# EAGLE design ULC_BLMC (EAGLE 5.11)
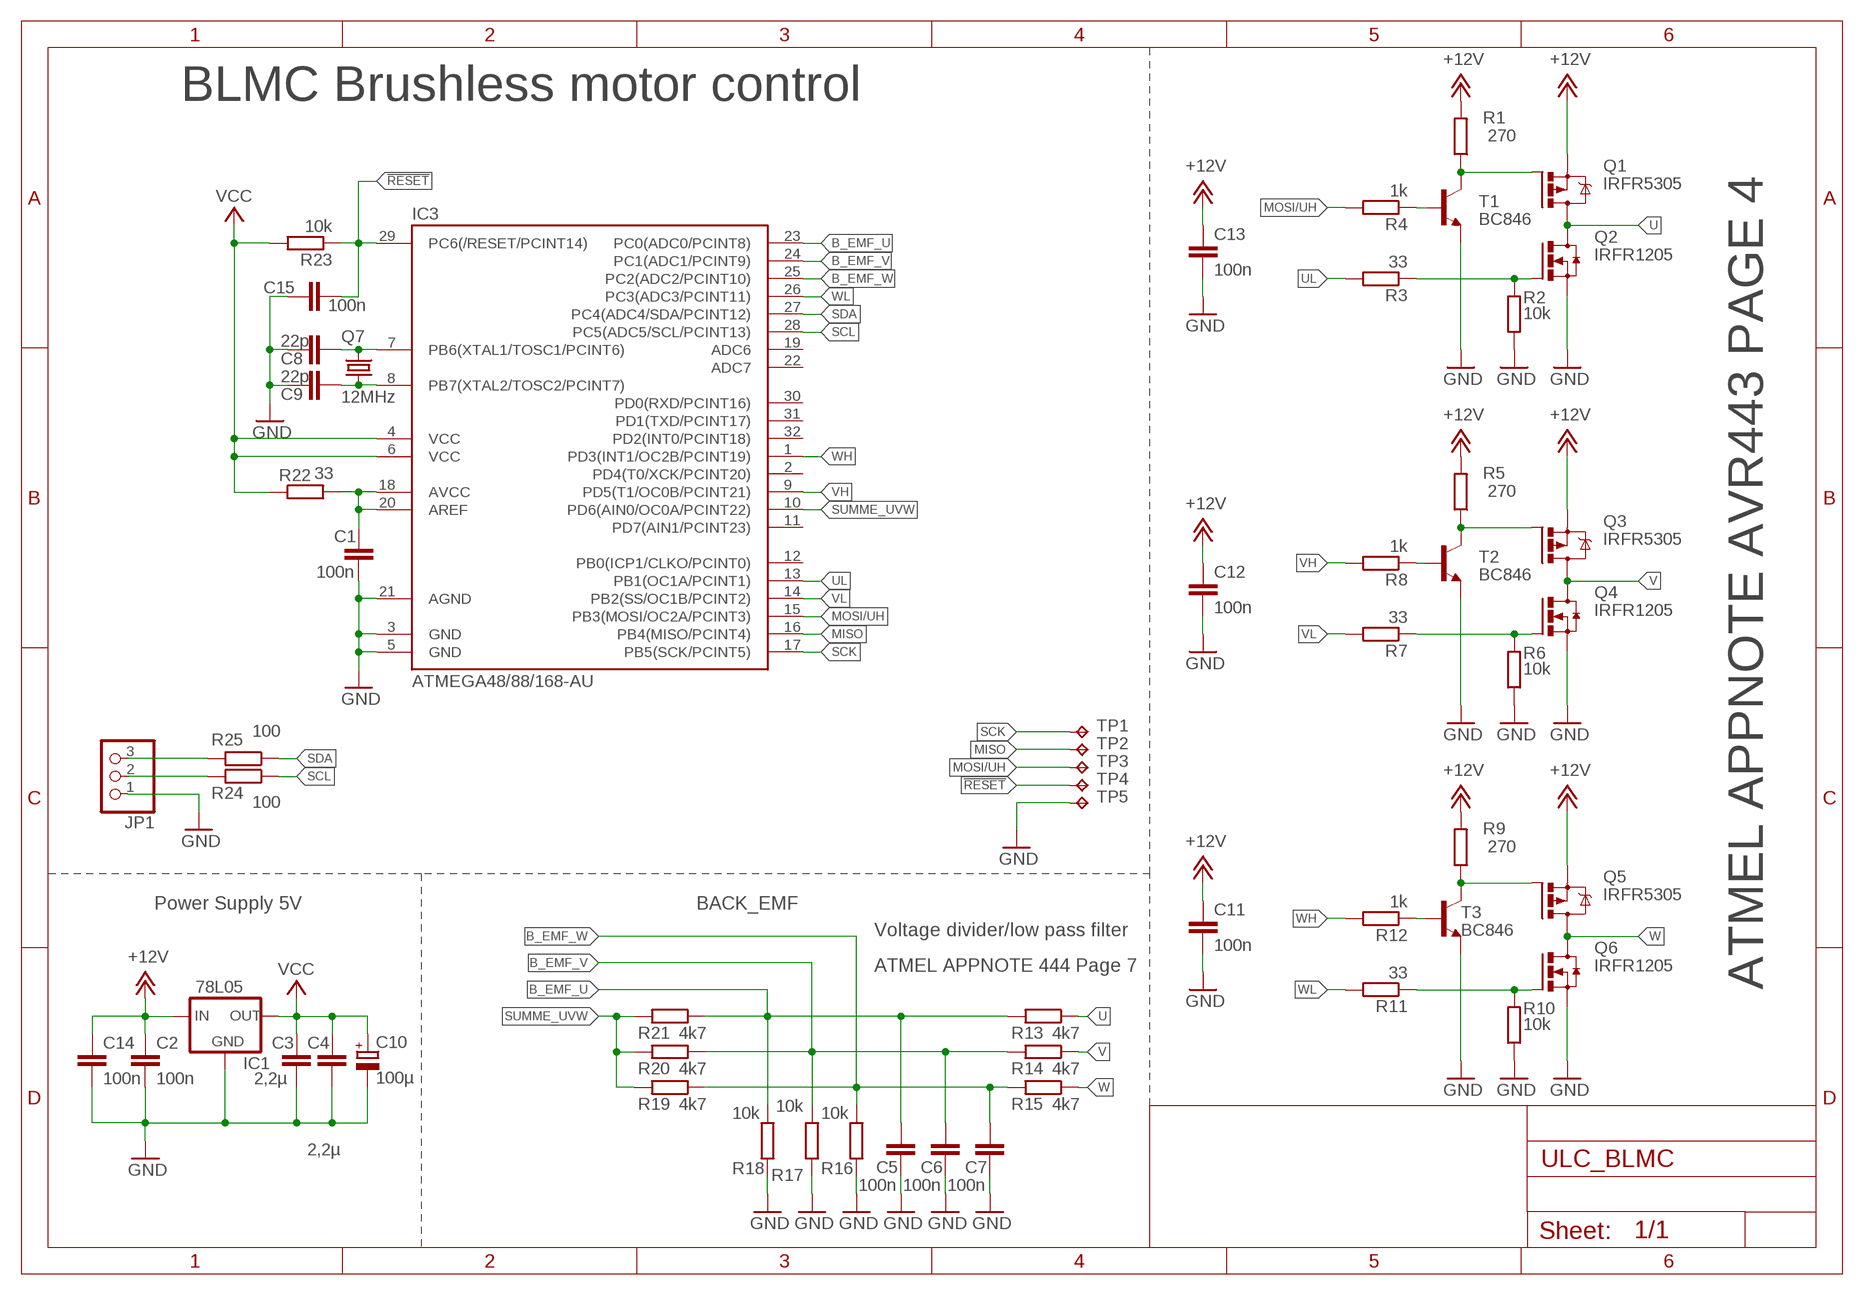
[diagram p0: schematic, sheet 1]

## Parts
C1  100n  C-EUC0805  [C0805]
C2  100n  C-EUC0805  [C0805]
C3  2,2µ  C-EUC0805  [C0805]
C4  2,2µ  C-EUC0805  [C0805]
C5  100n  C-EUC0805  [C0805]
C6  100n  C-EUC0805  [C0805]
C7  100n  C-EUC0805  [C0805]
C8  22p  C-EUC0805  [C0805]
C9  22p  C-EUC0805  [C0805]
C10  100µ  CPOL-EUSMCE  [SMC_E]
C11  100n  C-EUC0805  [C0805]
C12  100n  C-EUC0805  [C0805]
C13  100n  C-EUC0805  [C0805]
C14  100n  C-EUC0805  [C0805]
C15  100n  C-EUC0805  [C0805]
IC1  78L05  78LXX  [78LXX]
IC3  ATMEGA48/88/168-AU  [TQFP32-08]
JP1  PINHD-1X3  [1X03]
Q1  IRFR5305  [D-PAK_TO252AA]
Q2  IRFR1205  [D-PAK_TO252AA]
Q3  IRFR5305  [D-PAK_TO252AA]
Q4  IRFR1205  [D-PAK_TO252AA]
Q5  IRFR5305  [D-PAK_TO252AA]
Q6  IRFR1205  [D-PAK_TO252AA]
Q7  12MHz  CRYSTALCTS406  [CTS406]
R1  270  R-EU_M0805  [M0805]
R2  10k  R-EU_M0805  [M0805]
R3  33  R-EU_M0805  [M0805]
R4  1k  R-EU_M0805  [M0805]
R5  270  R-EU_M0805  [M0805]
R6  10k  R-EU_M0805  [M0805]
R7  33  R-EU_M0805  [M0805]
R8  1k  R-EU_M0805  [M0805]
R9  270  R-EU_M0805  [M0805]
R10  10k  R-EU_M0805  [M0805]
R11  33  R-EU_M0805  [M0805]
R12  1k  R-EU_M0805  [M0805]
R13  4k7  R-EU_M0805  [M0805]
R14  4k7  R-EU_M0805  [M0805]
R15  4k7  R-EU_M0805  [M0805]
R16  10k  R-EU_M0805  [M0805]
R17  10k  R-EU_M0805  [M0805]
R18  10k  R-EU_M0805  [M0805]
R19  4k7  R-EU_M0805  [M0805]
R20  4k7  R-EU_M0805  [M0805]
R21  4k7  R-EU_M0805  [M0805]
R22  33  R-EU_M0805  [M0805]
R23  10k  R-EU_M0805  [M0805]
R24  100  R-EU_M0805  [M0805]
R25  100  R-EU_M0805  [M0805]
T1  BC846  [SOT23]
T2  BC846  [SOT23]
T3  BC846  [SOT23]
TP1  TPB1,27  [B1,27]
TP2  TPB1,27  [B1,27]
TP3  TPB1,27  [B1,27]
TP4  TPB1,27  [B1,27]
TP5  TPB1,27  [B1,27]

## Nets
!RESET: C15.2 IC3.29(PC6(/RESET/PCINT14)) R23.1 TP4.TP
+12V: C2.1 C11.1 C12.1 C13.1 C14.1 IC1.IN Q1.3(S) Q3.3(S) Q5.3(S) R1.2 R5.2 R9.2
B_EMF_U: C5.1 IC3.23(PC0(ADC0/PCINT8)) R13.2 R18.1 R21.1
B_EMF_V: C6.1 IC3.24(PC1(ADC1/PCINT9)) R14.2 R17.1 R20.1
B_EMF_W: C7.1 IC3.25(PC2(ADC2/PCINT10)) R15.2 R16.1 R19.1
GND: C1.2 C2.2 C3.2 C4.2 C5.2 C6.2 C7.2 C8.1 C9.1 C10.- C11.2 C12.2 C13.2 C14.2 C15.1 IC1.GND IC3.3(GND) IC3.5(GND) IC3.21(AGND) JP1.1 Q2.3(S) Q4.3(S) Q6.3(S) R2.1 R6.1 R10.1 R16.2 R17.2 R18.2 T1.2(E) T2.2(E) T3.2(E) TP5.TP
MISO: IC3.16(PB4(MISO/PCINT4)) TP2.TP
MOSI/UH: IC3.15(PB3(MOSI/OC2A/PCINT3)) R4.2 TP3.TP
N$1: Q6.1(G) R10.2 R11.1
N$2: R4.1 T1.1(B)
N$3: C1.1 IC3.18(AVCC) IC3.20(AREF) R22.2
N$4: Q1.1(G) R1.1 T1.3(C)
N$5: Q3.1(G) R5.1 T2.3(C)
N$6: Q4.1(G) R6.2 R7.1
N$7: R8.1 T2.1(B)
N$8: Q5.1(G) R9.1 T3.3(C)
N$9: Q2.1(G) R2.2 R3.1
N$10: R12.1 T3.1(B)
N$11: C8.2 IC3.7(PB6(XTAL1/TOSC1/PCINT6)) Q7.3
N$12: C9.2 IC3.8(PB7(XTAL2/TOSC2/PCINT7)) Q7.1
N$13: JP1.3 R25.2
N$14: JP1.2 R24.2
SCK: IC3.17(PB5(SCK/PCINT5)) TP1.TP
SCL: IC3.28(PC5(ADC5/SCL/PCINT13)) R24.1
SDA: IC3.27(PC4(ADC4/SDA/PCINT12)) R25.1
SUMME_UVW: IC3.10(PD6(AIN0/OC0A/PCINT22)) R19.2 R20.2 R21.2
U: Q1.4(D) Q2.4(D) R13.1
UL: IC3.13(PB1(OC1A/PCINT1)) R3.2
V: Q3.4(D) Q4.4(D) R14.1
VCC: C3.1 C4.1 C10.+ IC1.OUT IC3.4(VCC) IC3.6(VCC) R22.1 R23.2
VH: IC3.9(PD5(T1/OC0B/PCINT21)) R8.2
VL: IC3.14(PB2(SS/OC1B/PCINT2)) R7.2
W: Q5.4(D) Q6.4(D) R15.1
WH: IC3.1(PD3(INT1/OC2B/PCINT19)) R12.2
WL: IC3.26(PC3(ADC3/PCINT11)) R11.2
Unconnected: IC3.2(PD4(T0/XCK/PCINT20)) IC3.11(PD7(AIN1/PCINT23)) IC3.12(PB0(ICP1/CLKO/PCINT0)) IC3.19(ADC6) IC3.22(ADC7) IC3.30(PD0(RXD/PCINT16)) IC3.31(PD1(TXD/PCINT17)) IC3.32(PD2(INT0/PCINT18))

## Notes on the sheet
- BLMC Brushless motor control
- Power Supply 5V | BACK_EMF
- Voltage divider/low pass filter
- ATMEL APPNOTE 444 Page 7
- ATMEL APPNOTE AVR443 PAGE 4

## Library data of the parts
C1-C9 C11-C15 = rcl:C-EU: CAPACITOR, European symbol
C10 = rcl:CPOL-EU: POLARIZED CAPACITOR, European symbol
IC1 = v-reg:78LXX: VOLTAGE REGULATOR
IC3 = atmega8:ATMEGA48/88/168
JP1 = pinhead:PINHD-1X3: PIN HEADER
Q1 Q3 Q5 = transistor-power:IRF?5305: HEXFET Power MOSFET Source: http://www.irf.com/product-info/datasheets/data/irfr5305pbf.pdf
Q2 Q4 Q6 = transistor-power:IRFR1205
Q7 = crystal:CRYSTAL: CRYSTAL; OC_FARNELL: unknown; OC_NEWARK: unknown
R1-R25 = rcl:R-EU_: RESISTOR, European symbol
T1-T3 = transistor:BC846: NPN TRANSISTOR
TP1-TP5 = testpad:TP: Test pad

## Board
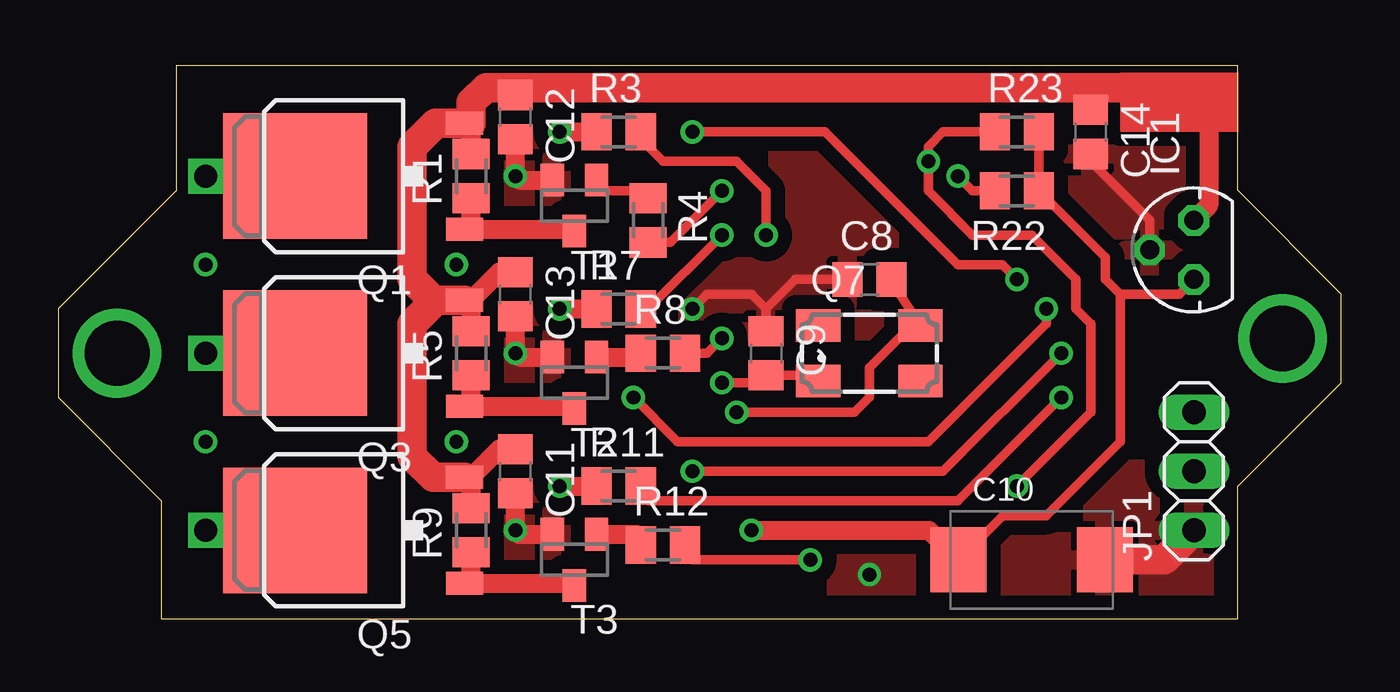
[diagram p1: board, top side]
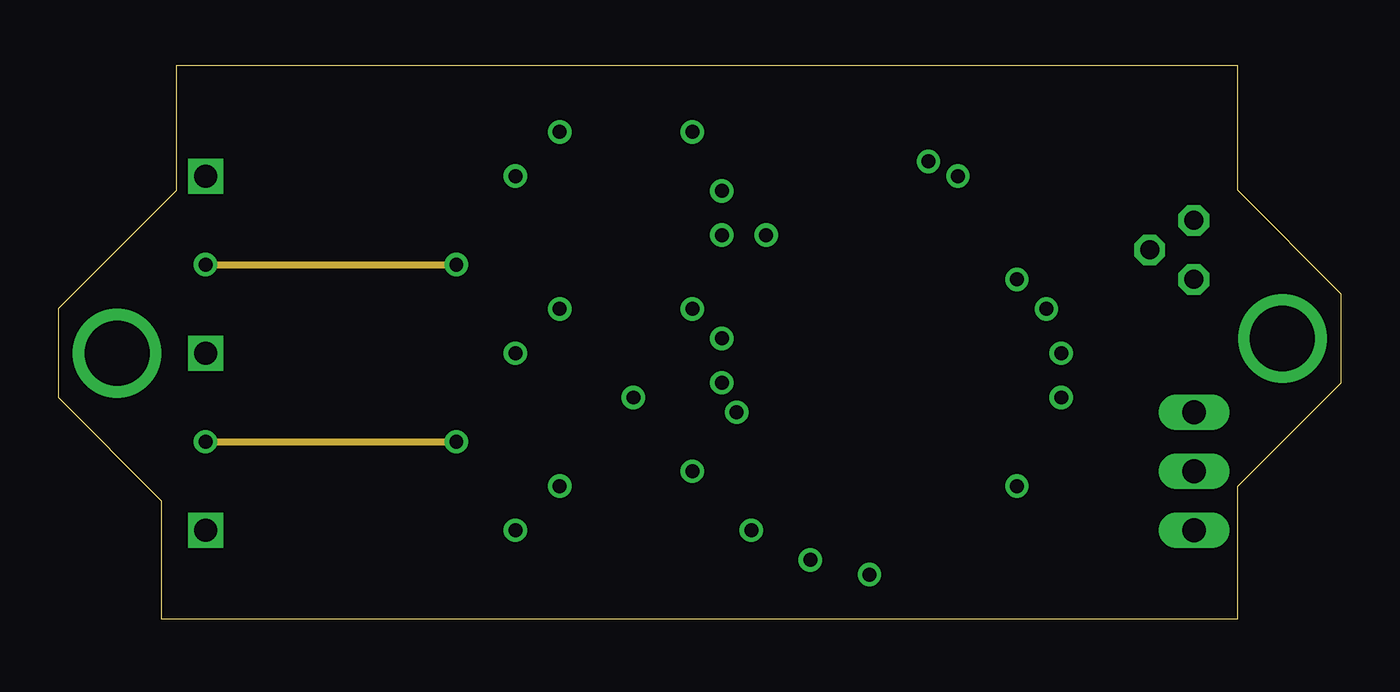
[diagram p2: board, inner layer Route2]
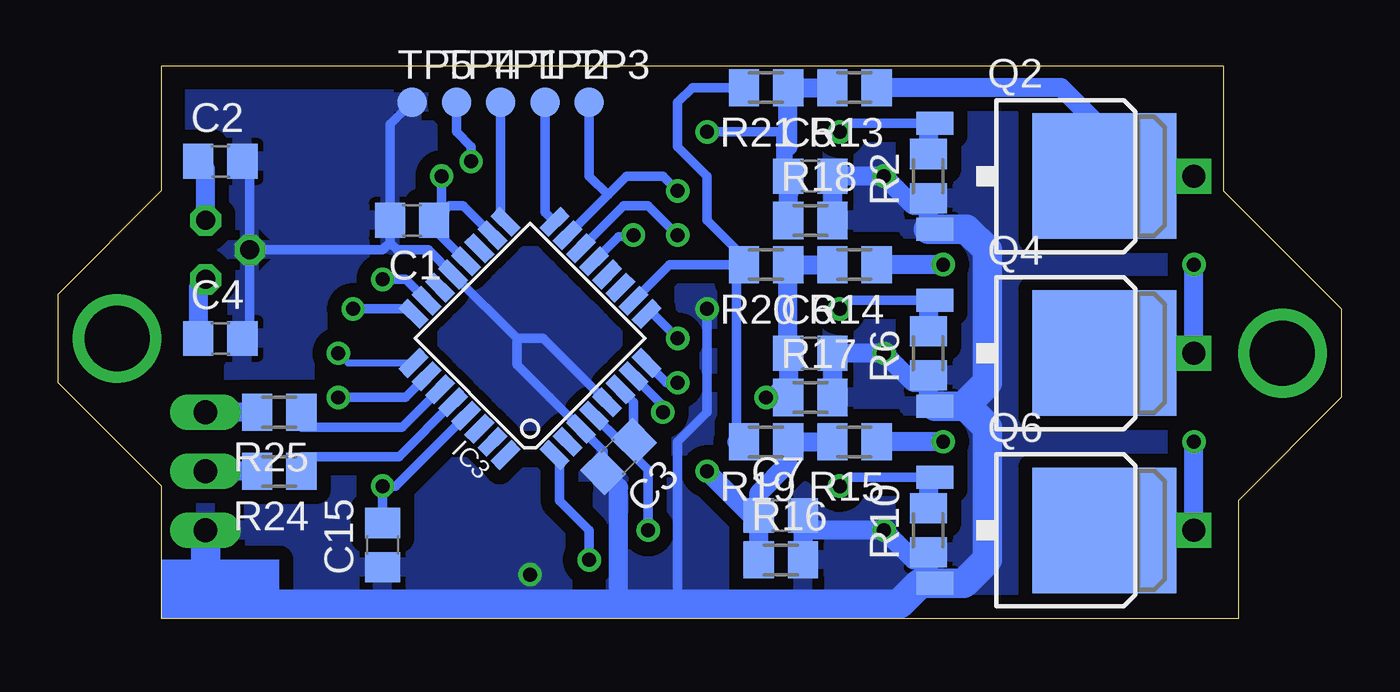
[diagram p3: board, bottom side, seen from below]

Size 55.24 x 23.8 mm. Coordinates in mm from the lower left corner, seen from the top.
Outline: 4.45,0 50.78,0 50.78,5.69 55.24,10.16 55.24,13.97 50.78,18.43 50.78,23.8 5.08,23.8 5.08,18.41 0,13.33 0,9.53 4.45,5.08 4.45,0
Copper layers (1*2*16): Top 0.035mm / dielectric 1.5mm / Route2 0.035mm / dielectric 0.15mm / Bottom 0.035mm
Design rules "default *": minimum track width 10mil, minimum drill 24mil, track to track 8mil, track to pad 8mil, pad to pad 8mil, via to via 8mil, smd to smd 8mil, copper to edge 40mil, drill to drill 8mil, minimum pad ring 10mil, minimum via ring 8mil, stop-mask expansion 4mil, vias tented up to drill 0mil, thermal gap 10mil

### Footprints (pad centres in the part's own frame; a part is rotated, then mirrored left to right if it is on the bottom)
C0805 = smd 1.3 x 1.5: 1 -0.95,0; 2 0.95,0
SMC_E = smd 2.4 x 2.8: + -3.15,0; - 3.15,0
78LXX = drill 0.813 octagon: GND 0,1.905; IN 1.27,0; OUT -1.27,0
TQFP32-08 = smd 1.27 x 0.559: 1 -4.293,2.8; 2 -4.293,2; 3 -4.293,1.2; 4 -4.293,0.4; 5 -4.293,-0.4; 6 -4.293,-1.2; 7 -4.293,-2; 8 -4.293,-2.8; 17 4.293,-2.8; 18 4.293,-2; 19 4.293,-1.2; 20 4.293,-0.4; 21 4.293,0.4; 22 4.293,1.2; 23 4.293,2; 24 4.293,2.8 | smd 0.559 x 1.27: 9 -2.8,-4.293; 10 -2,-4.293; 11 -1.2,-4.293; 12 -0.4,-4.293; 13 0.4,-4.293; 14 1.2,-4.293; 15 2,-4.293; 16 2.8,-4.293; 25 2.8,4.293; 26 2,4.293; 27 1.2,4.293; 28 0.4,4.293; 29 -0.4,4.293; 30 -1.2,4.293; 31 -2,4.293; 32 -2.8,4.293
1X03 = drill 1.016 long: 1 -2.54,0; 2 0,0; 3 2.54,0
D-PAK_TO252AA = smd 1 x 1.6: 1 -2.28,-4.8; 3 2.28,-4.8 | smd 5.4 x 6.2: 4 0,2.5
CTS406 = smd 1.9 x 1.4: 1 -2.2,-1.2; 2 2.2,-1.2; 3 2.2,1.2; 4 -2.2,1.2
M0805 = smd 1.3 x 1.6: 1 -0.95,0; 2 0.95,0
SOT23 = smd 1 x 1.4: 1 -0.95,-1.1; 2 0.95,-1.1; 3 0,1.1
B1,27 = smd 1.27 x 1.27: TP 0,0

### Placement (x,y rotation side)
C1  40.01,17.14 180 bottom
C2  48.26,19.69 0 bottom
C3  31.11,6.98 225 bottom
C4  48.26,12.06 0 bottom
C5  22.86,19.05 0 bottom
C6  22.86,11.43 0 bottom
C7  24.13,4.44 0 bottom
C8  34.92,14.61 0 top
C9  30.48,11.43 270 top
C10  41.91,2.54 0 top
C11  19.68,6.35 270 top
C12  19.68,21.59 270 top
C13  19.68,13.97 270 top
C14  44.45,20.95 270 top
C15  41.27,3.17 90 bottom
IC1  48.89,15.88 90 top
IC3  34.92,12.06 135 bottom
JP1  48.89,6.35 90 top
Q1  12.7,19.05 90 top
Q2  12.7,19.05 270 bottom
Q3  12.7,11.43 90 top
Q4  12.7,11.43 270 bottom
Q5  12.7,3.81 90 top
Q6  12.7,3.81 270 bottom
Q7  34.92,11.43 0 top
R1  17.78,19.05 90 top
R2  17.78,19.05 90 bottom
R3  24.13,20.95 0 top
R4  25.4,17.14 270 top
R5  17.78,11.43 90 top
R6  17.78,11.43 90 bottom
R7  24.13,13.33 0 top
R8  26.04,11.43 0 top
R9  17.78,3.81 90 top
R10  17.78,3.81 90 bottom
R11  24.13,5.71 0 top
R12  26.04,3.17 0 top
R13  20.95,22.86 180 bottom
R14  20.95,15.24 180 bottom
R15  20.95,7.62 180 bottom
R16  24.13,2.54 0 bottom
R17  22.86,9.53 0 bottom
R18  22.86,17.14 0 bottom
R19  24.77,7.62 180 bottom
R20  24.77,15.24 180 bottom
R21  24.77,22.86 180 bottom
R22  41.27,18.41 180 top
R23  41.27,20.95 0 top
R24  45.72,6.35 180 bottom
R25  45.72,8.89 180 bottom
T1  22.22,17.78 180 top
T2  22.22,10.16 180 top
T3  22.22,2.54 180 top
TP1  36.2,22.23 0 bottom
TP2  34.29,22.23 0 bottom
TP3  32.38,22.23 0 bottom
TP4  38.1,22.23 0 bottom
TP5  40.01,22.23 0 bottom

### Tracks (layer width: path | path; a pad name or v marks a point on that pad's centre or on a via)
!RESET  (via drill 0.6)
  Top 0.406: v41.27,5.71 44.45,8.89 44.45,12.7 43.81,13.33 43.81,14.61 41.91,16.51 39.37,16.51 37.46,18.41 v37.46,19.69 37.46,20.32 38.1,20.95 R23.1
  Bottom 0.406: IC3.29 40.71,5.71 v41.27,5.71 C15.2 | v37.46,19.69 37.46,20.32 38.1,20.95 TP4.TP
+12V
  Top 0.406: Q1.3 17.78,21.33 | 17.78,13.71 Q3.3 16.25,13.71 | Q5.3 17.78,6.09 | 18.41,22.86 19.36,22.86 C12.1
  Top 0.813: 17.78,21.33 R1.2 | R5.2 17.78,13.71 18.99,14.92 C13.1 | R9.2 17.78,6.09 18.99,7.3 C11.1 | 49.53,22.86 49.53,17.78 IC1.IN | 44.45,22.86 C14.1
  Top 1.27: Q5.3 16.14,6.09 15.24,6.98 15.24,12.7 16.25,13.71 | Q3.3 16.14,13.71 15.24,14.61 15.24,20.32 16.25,21.33 Q1.3 | 17.78,21.33 17.78,22.23 18.41,22.86 44.45,22.86 49.53,22.86
  Bottom 0.305: 48.89,19.37 C2.1
  Bottom 0.813: IC1.IN 48.89,19.37
B_EMF_U  (via drill 0.6)
  Top 0.406: v41.27,14.61 40.64,15.24 38.73,15.24 33.02,20.95 v27.3,20.95
  Bottom 0.406: R13.2 | C5.1 23.81,20.32 | IC3.23 40.29,14.61 v41.27,14.61 | 23.49,18.41 23.49,18.73 R18.1 24.13,19.05 24.13,20.95 v27.3,20.95
  Bottom 0.813: R13.2 R21.1 23.81,20.32 | R18.1 C5.1
B_EMF_V  (via drill 0.6)
  Top 0.406: v24.77,9.53 26.67,7.62 37.46,7.62 42.55,12.7 v42.55,13.33
  Bottom 0.406: R14.2 | C6.1 23.81,10.47 v24.77,9.53 | IC3.24 40.16,13.33 v42.55,13.33
  Bottom 0.813: R14.2 R20.1 C6.1 | C6.1 R17.1
B_EMF_W  (via drill 0.6)
  Top 0.406: v27.3,6.35 38.1,6.35 v43.18,11.43
  Bottom 0.305: IC3.25 42.76,11.01 v43.18,11.43
  Bottom 0.406: R15.2
  Bottom 0.813: R15.2 R19.1 23.81,6.67 25.08,5.4 C7.1 | R16.1 C7.1 | C7.1 25.4,4.44 v27.3,6.35
GND  (via drill 0.6)
  Top 0.406: v27.3,13.33 27.94,13.97 29.84,13.97 30.48,13.33 | C8.1 31.75,14.61 30.48,13.33 | 30.48,13.33 C9.1 | C14.2 44.45,19.69 46.99,17.14 IC1.GND
  Top 0.813: T3.2 19.86,3.64 v19.68,3.81 C11.2 | T2.2 19.86,11.26 v19.68,11.43 C13.2 | T1.2 19.86,18.88 v19.68,19.05 C12.2
  Top 1.27: C10.- 47.62,2.54 JP1.1
  Bottom 0.305: Q4.3 16.25,9.15 | 46.99,19.36 C2.2 | 46.99,12.06 C4.2
  Bottom 0.406: 17.78,16.77 Q2.3 | Q4.3 17.78,9.15 | Q6.3 17.78,1.53 | R6.1 18.1,10.16 | R10.1 18.1,2.54 | R2.1 18.1,17.78 | IC3.3 34.08,9.53 | v27.3,13.33 27.3,8.89 28.57,7.62 28.57,0.63 | IC3.5 34.36,12.06 35.49,12.06 | 35.49,12.06 IC3.21 39.3,15.88 40.64,15.88 40.95,16.19 | IC3.3 35.49,10.93 35.49,12.06 | IC3.3 31.79,7.23 C3.2 | TP5.TP 40.95,21.27 C1.2 40.95,16.19 | 49.53,0.63 48.89,1.27 | IC1.GND 46.99,19.36 | IC1.GND 46.99,12.06 | IC1.GND 41.27,15.88 40.95,16.19
  Bottom 0.813: 17.78,16.77 R2.1 | 17.78,9.15 R6.1 | 17.78,1.53 R10.1 | R18.2 C5.2 v19.68,19.05 18.41,17.78 18.1,17.78 | R17.2 C6.2 v19.68,11.43 18.41,10.16 18.1,10.16 | 23.18,3.81 C7.2 | 23.18,3.81 R16.2 | Q6.3 17.88,1.9 | 18.1,2.54 18.41,2.54 v19.68,3.81 23.18,3.81 | 31.11,0.63 31.11,5.64 C3.2
  Bottom 1.27: 17.78,16.77 16.14,16.77 15.24,15.88 15.24,10.16 16.25,9.15 | Q4.3 16.14,9.15 15.24,8.25 15.24,2.54 16.25,1.53 Q6.3 18.16,1.53 19.05,0.63 28.57,0.63 31.11,0.63 49.53,0.63 | 48.89,1.27 JP1.1
  other vias: 34.92,1.9
  pour Bottom (isolate 0.61): 0,23.49 0,0 55.88,0 55.88,23.49
  pour Top (isolate 0.61): 0,23.49 0,0 55.88,0 55.88,23.49
MISO
  Bottom 0.406: IC3.16 34.29,17.5 TP2.TP
MOSI/UH  (via drill 0.6)
  Top 0.406: R4.2 26.36,16.2 v28.57,18.41
  Bottom 0.406: 31.58,18.24 IC3.15 | TP3.TP 32.38,19.05 31.58,18.24 | 31.58,18.24 30.77,19.05 29.21,19.05 v28.57,18.41
N$1  (via drill 0.6)
  Top 0.813: v21.59,5.71 R11.1
  Bottom 0.406: Q6.1 17.78,6.09 21.21,6.09 v21.59,5.71
  Bottom 0.813: 17.78,6.09 R10.2
N$2
  Top 0.406: R4.1 25.4,18.41 23.64,18.41 arc-90 T1.1
N$3  (via drill 0.6)
  Top 0.406: 40.64,18.41 R22.2 39.37,18.41 v38.73,19.05
  Bottom 0.406: IC3.18 37.81,17.78 38.42,17.78 C1.1 | IC3.20 39.05,16.76 C1.1 | v38.73,19.05 38.73,17.46 C1.1
N$4
  Top 0.406: Q1.1 17.78,16.77 | R1.1 17.78,17.78 | 22.13,16.77 T1.3
  Top 0.813: R1.1 17.78,16.77 22.13,16.77
N$5
  Top 0.406: Q3.1 17.78,9.15 | R5.1 17.78,10.16 | 22.13,9.15 T2.3
  Top 0.813: R5.1 17.78,9.15 22.13,9.15
N$6  (via drill 0.6)
  Top 0.813: v21.59,13.33 R7.1
  Bottom 0.406: Q4.1 17.78,13.71 21.21,13.71 v21.59,13.33
  Bottom 0.813: 17.78,13.71 R6.2
N$7
  Top 0.406: 24.91,11.26 R8.1
  Top 0.813: T2.1 24.91,11.26
N$8
  Top 0.406: Q5.1 17.78,1.53 | R9.1 17.78,2.54 | 22.13,1.53 T3.3
  Top 0.813: R9.1 17.78,1.53 22.13,1.53
N$9  (via drill 0.6)
  Top 0.813: v21.59,20.95 R3.1
  Bottom 0.406: Q2.1 17.78,21.33 21.21,21.33 v21.59,20.95
  Bottom 0.813: 17.78,21.33 R2.2
N$10
  Top 0.406: 24.91,3.64 R12.1
  Top 0.813: T3.1 24.91,3.64
N$11  (via drill 0.6)
  Top 0.406: Q7.3 37.38,12.38 | v29.21,8.89 34.29,8.89 34.92,9.53 34.92,10.79 36.76,12.63 Q7.3 | C8.2 35.88,14.52 Q7.3
  Bottom 0.406: IC3.7 29.21,9.18 v29.21,8.89
N$12  (via drill 0.6)
  Top 0.406: Q7.1 32.48,10.48 C9.2 30.16,10.16 v28.57,10.16
  Bottom 0.406: IC3.8 29.06,10.16 v28.57,10.16
N$13
  Bottom 0.813: R25.2 JP1.3
N$14
  Bottom 0.813: R24.2 JP1.2
N$15  (via drill 2.8)
  other vias: 52.7,12.06
N$16  (via drill 2.8)
  other vias: 2.54,11.43
SCK
  Bottom 0.406: IC3.17 36.2,17.3 TP1.TP
SCL
  Bottom 0.406: IC3.28 40.57,6.98 44.77,6.98 R24.1
SDA
  Bottom 0.406: IC3.27 40.43,8.25 44.77,8.25 R25.1
SUMME_UVW
  Bottom 0.406: 26.04,7.62 26.04,15.24 | IC3.10 28.92,15.24 26.04,15.24 | 26.04,15.24 26.04,15.88 27.3,17.14 27.3,19.05 28.57,20.32 28.57,22.23 27.94,22.86 R21.2
  Bottom 0.813: 26.04,15.24 R20.2 | R19.2 26.04,7.62
U  (via drill 1)
  Top 1.27: v6.35,19.05 Q1.4
  Bottom 0.813: 8.25,19.05 12.07,22.86 R13.1
  Bottom 1.27: Q1.4 8.25,19.05 v6.35,19.05
UL  (via drill 0.6)
  Top 0.406: R3.2 24.77,20.95 26.04,19.69 29.21,19.69 30.48,18.41 v30.48,16.51
  Bottom 0.406: IC3.13 31.11,16.44 v30.48,16.51
V  (via drill 0.6, 1)
  Top 1.27: v6.35,11.43 Q3.4
  Route2 0.305: v6.35,15.24 v17.14,15.24
  Bottom 0.813: v6.35,11.43 v6.35,15.24 | v17.14,15.24 R14.1
  Bottom 1.27: v6.35,11.43 Q3.4
VCC  (via drill 0.6)
  Top 0.406: 45.72,13.97 45.72,7.62 42.55,4.44 40.66,4.44 C10.+ | 45.72,13.97 48.26,13.97 IC1.OUT | R23.2 R22.1 45.09,15.55 45.09,14.61 45.72,13.97
  Top 0.813: v29.84,3.81 37.49,3.81 C10.+
  Bottom 0.406: IC3.6 30.48,9.32 30.48,8.25 30.44,8.22 C3.1 31.08,7.66 IC3.4 29.84,6.42 v29.84,3.81
  Bottom 0.813: C4.1 49.21,14.29 IC1.OUT
VH  (via drill 0.6)
  Top 0.406: R8.2 27.94,11.43 v28.57,12.06
  Bottom 0.406: IC3.9 29.63,13.12 v28.57,12.06
VL  (via drill 0.6)
  Top 0.406: v28.57,16.51 25.4,13.33 R7.2
  Bottom 0.406: IC3.14 30.91,17.78 29.84,17.78 v28.57,16.51
W  (via drill 0.6, 1)
  Top 1.27: Q5.4 v6.35,3.81
  Route2 0.305: v6.35,7.62 v17.14,7.62
  Bottom 0.813: v6.35,3.81 v6.35,7.62 | v17.14,7.62 R15.1
  Bottom 1.27: v6.35,3.81 Q5.4
WH  (via drill 0.6)
  Top 0.406: R12.2 26.98,3.5 27.3,2.54 v32.38,2.54
  Bottom 0.406: IC3.1 33.66,6.83 33.66,5.08 32.38,3.81 v32.38,2.54
WL  (via drill 0.6)
  Top 0.406: R11.2 25.4,5.08 38.73,5.08 v43.18,9.53
  Bottom 0.406: IC3.26 40.29,9.53 v43.18,9.53
(copper drawn outside any net)
  shapes: Bottom area x1, Top area x1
